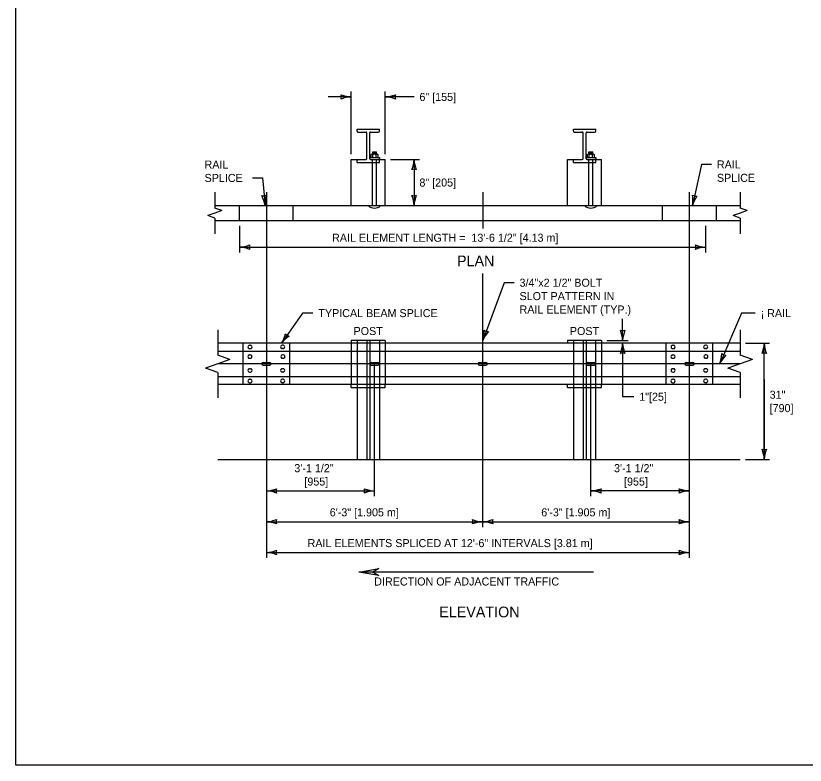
# Model space of a CAD drawing. Extents: x 49991.4 to 50021, y 49987.6 to 50011.4.
# Drawn here: x 49999.38 to 50005.28, y 49987.8 to 49993.4 of the extents above; entities that cross this region are included whole.
import ezdxf

# ---------------------------------------------------------------- set-up
doc = ezdxf.new("R2010")
doc.units = 0
for name, color, linetype in [('Level 1', 7, 'Continuous'), ('Level 2', 7, 'Continuous'), ('Level 3', 7, 'Continuous'), ('Level 4', 7, 'Continuous'), ('Level 5', 7, 'Continuous'), ('Level 6', 7, 'Continuous')]:
    doc.layers.add(name, color=color, linetype=linetype)

msp = doc.modelspace()

# ---------------------------------------------------------------- linework, layer by layer
at = {"layer": 'Level 1'}
for p, q in [((50001.9344, 49992.5525), (50002.101, 49992.5525)), ((50001.9344, 49992.5358), (50001.9344, 49992.5525)), ((50001.94, 49992.5302), (50002.0011, 49992.5302)), ((50002.0066, 49992.3307), (50002.0066, 49992.5247)), ((50002.0288, 49992.3307), (50002.0288, 49992.5247)), ((50002.0344, 49992.5302), (50002.0955, 49992.5302)), ((50002.101, 49992.5358), (50002.101, 49992.5525)), ((50003.5511, 49992.5525), (50003.7177, 49992.5525)), ((50003.5511, 49992.5358), (50003.5511, 49992.5525)), ((50003.5567, 49992.5302), (50003.6178, 49992.5302)), ((50003.6233, 49992.3307), (50003.6233, 49992.5247)), ((50003.6455, 49992.3307), (50003.6455, 49992.5247)), ((50003.6511, 49992.5302), (50003.7122, 49992.5302)), ((50003.7177, 49992.5358), (50003.7177, 49992.5525)), ((50001.8906, 49991.9808), (50001.8906, 49992.3252)), ((50001.8906, 49992.3252), (50001.9344, 49992.3252)), ((50001.9344, 49992.303), (50001.9344, 49992.3252)), ((50001.94, 49992.3251), (50002.0011, 49992.3251)), ((50002.0288, 49992.3393), (50002.1027, 49992.3393)), ((50002.0344, 49992.3251), (50002.0955, 49992.3251)), ((50002.0371, 49992.3601), (50002.0371, 49992.3393)), ((50002.0852, 49992.3641), (50002.0449, 49992.364)), ((50002.0509, 49992.3818), (50002.0793, 49992.3818)), ((50002.0509, 49992.364), (50002.0509, 49992.3818)), ((50002.0509, 49992.3801), (50002.0793, 49992.3776)), ((50002.0509, 49992.3748), (50002.0793, 49992.3725)), ((50002.0509, 49992.3692), (50002.0793, 49992.3669)), ((50002.0525, 49992.3393), (50002.0525, 49992.3602)), ((50002.0775, 49992.3393), (50002.0775, 49992.36)), ((50002.0793, 49992.3641), (50002.0793, 49992.3818)), ((50002.0929, 49992.3393), (50002.0929, 49992.3602)), ((50002.101, 49992.303), (50002.101, 49992.3252)), ((50002.101, 49992.3252), (50002.1447, 49992.3252)), ((50002.1027, 49992.3393), (50002.1027, 49992.3252)), ((50002.1447, 49991.9808), (50002.1447, 49992.3252)), ((50003.5073, 49991.9808), (50003.5073, 49992.3252)), ((50003.5073, 49992.3252), (50003.5511, 49992.3252)), ((50003.5511, 49992.303), (50003.5511, 49992.3252)), ((50003.5567, 49992.3251), (50003.6178, 49992.3251)), ((50003.6455, 49992.3393), (50003.7194, 49992.3393)), ((50003.6511, 49992.3251), (50003.7122, 49992.3251)), ((50003.6538, 49992.3601), (50003.6538, 49992.3393)), ((50003.7019, 49992.3641), (50003.6616, 49992.364)), ((50003.6676, 49992.3818), (50003.696, 49992.3818)), ((50003.6676, 49992.364), (50003.6676, 49992.3818)), ((50003.6676, 49992.3801), (50003.696, 49992.3776)), ((50003.6676, 49992.3748), (50003.696, 49992.3725)), ((50003.6676, 49992.3692), (50003.696, 49992.3669)), ((50003.6692, 49992.3393), (50003.6692, 49992.3602)), ((50003.6942, 49992.3393), (50003.6942, 49992.36)), ((50003.696, 49992.3641), (50003.696, 49992.3818)), ((50003.7096, 49992.3393), (50003.7096, 49992.3602)), ((50003.7177, 49992.303), (50003.7177, 49992.3252)), ((50003.7177, 49992.3252), (50003.7614, 49992.3252)), ((50003.7194, 49992.3393), (50003.7194, 49992.3252)), ((50003.7614, 49991.9808), (50003.7614, 49992.3252)), ((50001.9344, 49992.303), (50002.101, 49992.303)), ((50003.5511, 49992.303), (50003.7177, 49992.303)), ((50000.872, 49991.9808), (50004.7972, 49991.9808)), ((50001.0555, 49991.8697), (50001.0555, 49991.9808)), ((50004.2174, 49991.8697), (50004.2174, 49991.9808)), ((50000.872, 49991.8697), (50004.7972, 49991.8697)), ((50001.8905, 49990.9734), (50001.8905, 49990.9514)), ((50002.1446, 49990.9734), (50001.8905, 49990.9734)), ((50002.1446, 49990.9734), (50002.1446, 49990.9514)), ((50003.5072, 49990.9734), (50003.5072, 49990.9514)), ((50003.7613, 49990.9734), (50003.5072, 49990.9734)), ((50003.7613, 49990.9734), (50003.7613, 49990.9514)), ((50004.7972, 49990.9514), (50000.8926, 49990.9514)), ((50001.0822, 49990.6438), (50001.0822, 49990.9514)), ((50001.1314, 49990.9371), (50001.1374, 49990.9371)), ((50001.1314, 49990.9119), (50001.1374, 49990.9119)), ((50001.3815, 49990.9371), (50001.3754, 49990.9371)), ((50001.3815, 49990.9119), (50001.3754, 49990.9119)), ((50004.2441, 49990.6438), (50004.2441, 49990.9514)), ((50004.2933, 49990.9371), (50004.2993, 49990.9371)), ((50004.2933, 49990.9119), (50004.2993, 49990.9119)), ((50004.5434, 49990.9371), (50004.5373, 49990.9371)), ((50004.5434, 49990.9119), (50004.5373, 49990.9119)), ((50004.7972, 49990.8913), (50000.8926, 49990.8913)), ((50001.1301, 49990.8647), (50001.1362, 49990.8647)), ((50001.3827, 49990.8647), (50001.3767, 49990.8647)), ((50004.292, 49990.8647), (50004.2981, 49990.8647)), ((50004.5446, 49990.8647), (50004.5386, 49990.8647)), ((50001.1301, 49990.8395), (50001.1362, 49990.8395)), ((50001.2322, 49990.8092), (50001.2809, 49990.8092)), ((50001.3827, 49990.8395), (50001.3767, 49990.8395)), ((50002.0406, 49990.8092), (50002.0892, 49990.8092)), ((50002.8489, 49990.8092), (50002.8976, 49990.8092)), ((50003.6573, 49990.8092), (50003.7059, 49990.8092)), ((50004.292, 49990.8395), (50004.2981, 49990.8395)), ((50004.3941, 49990.8092), (50004.4428, 49990.8092)), ((50004.5446, 49990.8395), (50004.5386, 49990.8395)), ((50001.1315, 49990.7613), (50001.1376, 49990.7613)), ((50001.1315, 49990.7361), (50001.1376, 49990.7361)), ((50001.2322, 49990.7884), (50001.2809, 49990.7884)), ((50001.3813, 49990.7613), (50001.3753, 49990.7613)), ((50001.3813, 49990.7361), (50001.3753, 49990.7361)), ((50002.0406, 49990.7884), (50002.0892, 49990.7884)), ((50002.8489, 49990.7884), (50002.8976, 49990.7884)), ((50003.6573, 49990.7884), (50003.7059, 49990.7884)), ((50004.2934, 49990.7613), (50004.2995, 49990.7613)), ((50004.2934, 49990.7361), (50004.2995, 49990.7361)), ((50004.3941, 49990.7884), (50004.4428, 49990.7884)), ((50004.5432, 49990.7613), (50004.5372, 49990.7613)), ((50004.5432, 49990.7361), (50004.5372, 49990.7361)), ((50004.7972, 49990.7013), (50000.8926, 49990.7013)), ((50001.1313, 49990.6825), (50001.1374, 49990.6825)), ((50001.3815, 49990.6825), (50001.3754, 49990.6825)), ((50004.2932, 49990.6825), (50004.2993, 49990.6825)), ((50004.5434, 49990.6825), (50004.5373, 49990.6825)), ((50004.7972, 49990.6438), (50000.8926, 49990.6438)), ((50001.1313, 49990.6573), (50001.1374, 49990.6573)), ((50001.3815, 49990.6573), (50001.3754, 49990.6573)), ((50001.8905, 49990.6218), (50001.8905, 49990.6438)), ((50001.8905, 49990.6218), (50002.1446, 49990.6218)), ((50001.9343, 49990.6218), (50001.9343, 49990.0834)), ((50002.1009, 49990.6218), (50002.1009, 49990.0834)), ((50002.1446, 49990.6218), (50002.1446, 49990.6438)), ((50003.5072, 49990.6218), (50003.5072, 49990.6438)), ((50003.5072, 49990.6218), (50003.7613, 49990.6218)), ((50003.551, 49990.6218), (50003.551, 49990.0834)), ((50003.7176, 49990.6218), (50003.7176, 49990.0834)), ((50003.7613, 49990.6218), (50003.7613, 49990.6438)), ((50004.2932, 49990.6573), (50004.2993, 49990.6573)), ((50004.5434, 49990.6573), (50004.5373, 49990.6573)), ((50000.8926, 49990.0834), (50004.7972, 49990.0834))]:
    msp.add_line(p, q, dxfattribs=at)
msp.add_lwpolyline([(49999.3835, 49998.9992), (50016.7501, 49998.9992), (50016.7501, 49987.7988), (49999.3835, 49987.7988)], close=True, dxfattribs=at)
for centre, radius, start, end in [((50001.94, 49992.5358), 0.00555, 180, 270), ((50002.0011, 49992.5247), 0.00555, 360, 90), ((50002.0344, 49992.5247), 0.00555, 90, 180), ((50002.0955, 49992.5358), 0.00555, 270, 360), ((50003.5567, 49992.5358), 0.00555, 180, 270), ((50003.6178, 49992.5247), 0.00555, 360, 90), ((50003.6511, 49992.5247), 0.00555, 90, 180), ((50003.7122, 49992.5358), 0.00555, 270, 360), ((50001.94, 49992.3196), 0.00555, 90, 177.19225), ((50002.0011, 49992.3307), 0.00555, 270, 360), ((50002.0344, 49992.3307), 0.00555, 180, 270), ((50002.0448, 49992.3543), 0.00966, 37.32412, 143.10465), ((50002.0649, 49992.3428), 0.0213, 53.6874, 125.33876), ((50002.0853, 49992.3547), 0.00937, 35.4686, 145.97891), ((50002.0955, 49992.3196), 0.00555, 2.80775, 90), ((50003.5567, 49992.3196), 0.00555, 90, 177.19225), ((50003.6178, 49992.3307), 0.00555, 270, 360), ((50003.6511, 49992.3307), 0.00555, 180, 270), ((50003.6615, 49992.3543), 0.00966, 37.32412, 143.10465), ((50003.6816, 49992.3428), 0.0213, 53.6874, 125.33876), ((50003.702, 49992.3547), 0.00937, 35.4686, 145.97891), ((50003.7122, 49992.3196), 0.00555, 2.80775, 90), ((50001.2322, 49990.7988), 0.0104, 90, 180), ((50001.2322, 49990.7988), 0.0104, 180, 270), ((50001.2809, 49990.7988), 0.0104, 360, 90), ((50001.2809, 49990.7988), 0.0104, 270, 0), ((50002.0406, 49990.7988), 0.0104, 90, 180), ((50002.0406, 49990.7988), 0.0104, 180, 270), ((50002.0892, 49990.7988), 0.0104, 360, 90), ((50002.0892, 49990.7988), 0.0104, 270, 0), ((50002.8489, 49990.7988), 0.0104, 90, 180), ((50002.8489, 49990.7988), 0.0104, 180, 270), ((50002.8976, 49990.7988), 0.0104, 360, 90), ((50002.8976, 49990.7988), 0.0104, 270, 0), ((50003.6573, 49990.7988), 0.0104, 90, 180), ((50003.6573, 49990.7988), 0.0104, 180, 270), ((50003.7059, 49990.7988), 0.0104, 360, 90), ((50003.7059, 49990.7988), 0.0104, 270, 0), ((50004.3941, 49990.7988), 0.0104, 90, 180), ((50004.3941, 49990.7988), 0.0104, 180, 270), ((50004.4428, 49990.7988), 0.0104, 360, 90), ((50004.4428, 49990.7988), 0.0104, 270, 0)]:
    msp.add_arc(centre, radius, start, end, dxfattribs=at)
for centre, major_axis, start_param, end_param in [((50001.1314, 49990.9245), (-0.0126, 0), 4.712389, 7.853982), ((50001.1374, 49990.9245), (-0.0126, 0), 1.570796, 4.712389), ((50001.3754, 49990.9245), (0.0126, 0), 1.570796, 4.712389), ((50001.3815, 49990.9245), (0.0126, 0), 4.712389, 7.853982), ((50004.2933, 49990.9245), (-0.0126, 0), 4.712389, 7.853982), ((50004.2993, 49990.9245), (-0.0126, 0), 1.570796, 4.712389), ((50004.5373, 49990.9245), (0.0126, 0), 1.570796, 4.712389), ((50004.5434, 49990.9245), (0.0126, 0), 4.712389, 7.853982), ((50001.1301, 49990.8521), (-0.0126, 0), 4.712389, 7.853982), ((50001.1362, 49990.8521), (-0.0126, 0), 1.570796, 4.712389), ((50001.3767, 49990.8521), (0.0126, 0), 1.570796, 4.712389), ((50001.3827, 49990.8521), (0.0126, 0), 4.712389, 7.853982), ((50004.292, 49990.8521), (-0.0126, 0), 4.712389, 7.853982), ((50004.2981, 49990.8521), (-0.0126, 0), 1.570796, 4.712389), ((50004.5386, 49990.8521), (0.0126, 0), 1.570796, 4.712389), ((50004.5446, 49990.8521), (0.0126, 0), 4.712389, 7.853982), ((50001.1315, 49990.7487), (-0.0126, 0), 4.712389, 7.853982), ((50001.1376, 49990.7487), (-0.0126, 0), 1.570796, 4.712389), ((50001.3753, 49990.7487), (0.0126, 0), 1.570796, 4.712389), ((50001.3813, 49990.7487), (0.0126, 0), 4.712389, 7.853982), ((50004.2934, 49990.7487), (-0.0126, 0), 4.712389, 7.853982), ((50004.2995, 49990.7487), (-0.0126, 0), 1.570796, 4.712389), ((50004.5372, 49990.7487), (0.0126, 0), 1.570796, 4.712389), ((50004.5432, 49990.7487), (0.0126, 0), 4.712389, 7.853982), ((50001.1313, 49990.6699), (-0.0126, 0), 4.712389, 7.853982), ((50001.1374, 49990.6699), (-0.0126, 0), 1.570796, 4.712389), ((50001.3754, 49990.6699), (0.0126, 0), 1.570796, 4.712389), ((50001.3815, 49990.6699), (0.0126, 0), 4.712389, 7.853982), ((50004.2932, 49990.6699), (-0.0126, 0), 4.712389, 7.853982), ((50004.2993, 49990.6699), (-0.0126, 0), 1.570796, 4.712389), ((50004.5373, 49990.6699), (0.0126, 0), 1.570796, 4.712389), ((50004.5434, 49990.6699), (0.0126, 0), 4.712389, 7.853982)]:
    msp.add_ellipse(centre, major_axis=major_axis, ratio=0.998676, start_param=start_param, end_param=end_param, dxfattribs=at)
at = {"layer": 'Level 3'}
for p, q in [((50001.8906, 49992.3652), (50001.8906, 49992.8325)), ((50002.1447, 49992.3652), (50002.1447, 49992.8325)), ((50001.8906, 49992.7925), (50001.7172, 49992.7925)), ((50002.3604, 49992.7925), (50002.1447, 49992.7925)), ((50002.1847, 49992.3252), (50002.4004, 49992.3252)), ((50002.3604, 49992.3252), (50002.3604, 49991.9808)), ((50004.5097, 49992.2882), (50004.4415, 49991.9808)), ((50004.5838, 49992.2882), (50004.5097, 49992.2882)), ((50001.1524, 49992.1874), (50001.2265, 49992.1874)), ((50001.2265, 49992.1874), (50001.2465, 49991.9808)), ((50001.0555, 49991.8297), (50001.0555, 49991.6305)), ((50004.5392, 49991.8297), (50004.5392, 49991.6305)), ((50001.0555, 49991.6705), (50004.5392, 49991.6705)), ((50003.0345, 49991.4043), (50002.8733, 49990.9734)), ((50003.1086, 49991.4043), (50003.0345, 49991.4043)), ((50001.527, 49991.1772), (50001.3693, 49990.9514)), ((50001.6049, 49991.1772), (50001.527, 49991.1772)), ((50004.8081, 49991.1772), (50004.6447, 49990.7988)), ((50004.9105, 49991.1772), (50004.8081, 49991.1772)), ((50003.9193, 49990.9734), (50003.9193, 49991.1336)), ((50003.8013, 49990.9734), (50003.9593, 49990.9734)), ((50003.9193, 49990.9514), (50003.9193, 49990.5523)), ((50004.8372, 49990.9514), (50005.018, 49990.9514)), ((50004.978, 49990.0834), (50004.978, 49990.9514)), ((50004.978, 49990.681), (50004.978, 49990.0903)), ((50004.0033, 49990.5523), (50003.9193, 49990.5523)), ((50004.8372, 49990.0834), (50005.018, 49990.0834)), ((50001.2566, 49989.8485), (50002.0649, 49989.8485)), ((50004.4185, 49989.8485), (50003.6816, 49989.8485)), ((50001.2566, 49989.6185), (50002.8733, 49989.6185)), ((50002.8733, 49989.6185), (50004.4185, 49989.6185)), ((50001.2566, 49989.3885), (50004.4185, 49989.3885)), ((50003.7011, 49989.2417), (50001.948, 49989.2417))]:
    msp.add_line(p, q, dxfattribs=at)
msp.add_lwpolyline([(50002.0969, 49989.2155), (50001.948, 49989.2417), (50002.0969, 49989.2681), (50002.0515, 49989.2417)], close=True, dxfattribs=at)
for centre, radius, start, end in [((50001.8998, 49993.0146), 0.2223, 247.45601, 267.63952), ((50001.7624, 49992.7925), 0.0548, 342.13882, 17.86118), ((50002.1332, 49993.0252), 0.233, 272.82731, 292.07716), ((50002.2729, 49992.7925), 0.0548, 162.13882, 197.86118), ((50001.9021, 49992.5598), 0.233, 92.82731, 112.07716), ((50002.1355, 49992.5704), 0.2223, 67.45601, 87.63952), ((50002.1382, 49992.3344), 0.2223, 337.45601, 357.63952), ((50002.5931, 49992.3367), 0.233, 182.82731, 202.07716), ((50002.3604, 49992.197), 0.0548, 72.13882, 107.86118), ((50001.2341, 49992.1084), 0.0548, 257.6606, 293.38296), ((50001.016, 49991.947), 0.233, 8.34909, 27.59894), ((50001.4685, 49991.9931), 0.2223, 162.97779, 183.1613), ((50002.3604, 49992.109), 0.0548, 252.13882, 287.86118), ((50002.1276, 49991.9693), 0.233, 2.82731, 22.07716), ((50002.5825, 49991.9716), 0.2223, 157.45601, 177.63952), ((50004.2226, 49992.02), 0.2223, 349.84315, 10.02666), ((50004.6662, 49991.9191), 0.233, 145.40551, 164.65536), ((50004.4693, 49992.106), 0.0548, 239.62149, 275.34385), ((50001.044, 49991.9032), 0.233, 272.82731, 292.07716), ((50001.1837, 49991.6705), 0.0548, 162.13882, 197.86118), ((50004.5483, 49991.8927), 0.2223, 247.45601, 267.63952), ((50004.4109, 49991.6705), 0.0548, 342.13882, 17.86118), ((50001.0463, 49991.4484), 0.2223, 67.45601, 87.63952), ((50004.5506, 49991.4378), 0.233, 92.82731, 112.07716), ((50002.6513, 49991.0442), 0.233, 342.30809, 1.55794), ((50003.0781, 49990.887), 0.2223, 136.93679, 157.1203), ((50002.9182, 49991.0935), 0.0548, 231.6196, 267.34196), ((50003.6971, 49990.9642), 0.2223, 2.36048, 22.54399), ((50003.9193, 49991.1016), 0.0548, 252.13882, 287.86118), ((50004.152, 49990.9619), 0.233, 157.92284, 177.17269), ((50001.1719, 49991.0753), 0.233, 327.88526, 347.13511), ((50001.5461, 49990.8167), 0.2223, 122.51396, 142.69747), ((50001.4427, 49991.0565), 0.0548, 217.19677, 252.91913), ((50003.6971, 49990.9606), 0.2223, 337.45601, 357.63952), ((50004.152, 49990.9629), 0.233, 182.82731, 202.07716), ((50004.7559, 49990.9606), 0.2223, 337.45601, 357.63952), ((50005.2107, 49990.9629), 0.233, 182.82731, 202.07716), ((50003.9193, 49990.8232), 0.0548, 72.13882, 107.86118), ((50004.4265, 49990.8805), 0.233, 339.4694, 358.71925), ((50004.845, 49990.7023), 0.2223, 134.0981, 154.28161), ((50004.6955, 49990.9165), 0.0548, 228.78091, 264.50327), ((50004.978, 49990.8232), 0.0548, 72.13882, 107.86118), ((50004.978, 49990.2116), 0.0548, 252.13882, 287.86118), ((50004.7453, 49990.0719), 0.233, 2.82731, 22.07716), ((50005.2001, 49990.0742), 0.2223, 157.45601, 177.63952), ((50001.2451, 49990.0812), 0.233, 272.82731, 292.07716), ((50001.2474, 49989.6263), 0.2223, 67.45601, 87.63952), ((50001.3848, 49989.8485), 0.0548, 162.13882, 197.86118), ((50002.0741, 49990.0706), 0.2223, 247.45601, 267.63952), ((50001.9367, 49989.8485), 0.0548, 342.13882, 17.86118), ((50002.0764, 49989.6157), 0.233, 92.82731, 112.07716), ((50003.6724, 49990.0706), 0.2223, 272.36048, 292.54399), ((50003.6701, 49989.6157), 0.233, 67.92284, 87.17269), ((50003.8098, 49989.8485), 0.0548, 162.13882, 197.86118), ((50004.2902, 49989.8485), 0.0548, 342.13882, 17.86118), ((50004.4299, 49990.0812), 0.233, 247.92284, 267.17269), ((50004.4276, 49989.6263), 0.2223, 92.36048, 112.54399), ((50001.2451, 49989.8512), 0.233, 272.82731, 292.07716), ((50001.2474, 49989.3963), 0.2223, 67.45601, 87.63952), ((50001.3848, 49989.6185), 0.0548, 162.13882, 197.86118), ((50002.8824, 49989.8406), 0.2223, 247.45601, 267.63952), ((50002.745, 49989.6185), 0.0548, 342.13882, 17.86118), ((50002.8847, 49989.3857), 0.233, 92.82731, 112.07716), ((50002.8618, 49989.8512), 0.233, 272.82731, 292.07716), ((50002.8641, 49989.3963), 0.2223, 67.45601, 87.63952), ((50003.0015, 49989.6185), 0.0548, 162.13882, 197.86118), ((50004.4276, 49989.8406), 0.2223, 247.45601, 267.63952), ((50004.2902, 49989.6185), 0.0548, 342.13882, 17.86118), ((50004.4299, 49989.3857), 0.233, 92.82731, 112.07716), ((50001.2451, 49989.6212), 0.233, 272.82731, 292.07716), ((50001.2474, 49989.1663), 0.2223, 67.45601, 87.63952), ((50001.3848, 49989.3885), 0.0548, 162.13882, 197.86118), ((50004.4276, 49989.6106), 0.2223, 247.45601, 267.63952), ((50004.2902, 49989.3885), 0.0548, 342.13882, 17.86118), ((50004.4299, 49989.1557), 0.233, 92.82731, 112.07716)]:
    msp.add_arc(centre, radius, start, end, dxfattribs=at)
at = {"layer": 'Level 4'}
for p, q in [((50002.0508, 49991.9808), (50002.0508, 49992.3251)), ((50002.079, 49991.9808), (50002.079, 49992.3251)), ((50003.6675, 49991.9808), (50003.6675, 49992.3251)), ((50003.6957, 49991.9808), (50003.6957, 49992.3251)), ((50001.4577, 49991.8697), (50001.4577, 49991.9808)), ((50004.6196, 49991.8697), (50004.6196, 49991.9808)), ((50001.9343, 49990.9734), (50001.9343, 49990.6218)), ((50002.0065, 49990.9734), (50002.0065, 49990.0834)), ((50002.0287, 49990.9734), (50002.0287, 49990.0834)), ((50002.1009, 49990.9734), (50002.1009, 49990.6218)), ((50003.551, 49990.9734), (50003.551, 49990.6218)), ((50003.6232, 49990.9734), (50003.6232, 49990.0834)), ((50003.6454, 49990.9734), (50003.6454, 49990.0834)), ((50003.7176, 49990.9734), (50003.7176, 49990.6218)), ((50001.4306, 49990.6438), (50001.4306, 49990.9514)), ((50001.8905, 49990.9514), (50001.8905, 49990.6438)), ((50002.1446, 49990.9514), (50002.1446, 49990.6438)), ((50003.7613, 49990.9514), (50003.7613, 49990.6438)), ((50004.5925, 49990.6438), (50004.5925, 49990.9514))]:
    msp.add_line(p, q, dxfattribs=at)
for centre in [(50002.0648, 49992.0302), (50003.6815, 49992.0302)]:
    msp.add_arc(centre, 0.0682, 226.38418, 313.61582, dxfattribs=at)
at = {"layer": 'Level 5'}
for p, q in [((50001.2566, 49992.0808), (50001.2566, 49989.3485)), ((50002.8733, 49992.0808), (50002.8733, 49991.8105)), ((50004.4185, 49989.3485), (50004.4185, 49992.0808)), ((50002.8733, 49989.5785), (50002.8733, 49991.4722)), ((50004.8005, 49990.7988), (50000.8959, 49990.7988)), ((50002.0649, 49989.8085), (50002.0649, 49990.7988)), ((50003.6816, 49989.8085), (50003.6816, 49990.7988))]:
    msp.add_line(p, q, dxfattribs=at)
at = {"layer": 'Level 6'}
for p, q in [((50000.872, 49992.0808), (50000.872, 49991.9618)), ((50004.7972, 49992.0808), (50004.7972, 49991.9618)), ((50000.872, 49991.9247), (50000.8197, 49991.9062)), ((50000.9244, 49991.9433), (50000.872, 49991.9618)), ((50000.9244, 49991.9433), (50000.872, 49991.9247)), ((50004.7972, 49991.9247), (50004.7449, 49991.9062)), ((50004.8496, 49991.9433), (50004.7972, 49991.9618)), ((50004.8496, 49991.9433), (50004.7972, 49991.9247)), ((50000.872, 49991.8876), (50000.8197, 49991.9062)), ((50000.872, 49991.8876), (50000.872, 49991.7697)), ((50004.7972, 49991.8876), (50004.7449, 49991.9062)), ((50004.7972, 49991.8876), (50004.7972, 49991.7697)), ((50000.8926, 49991.0514), (50000.8926, 49990.8624)), ((50004.7972, 49991.0514), (50004.7972, 49990.8624)), ((50000.984, 49990.83), (50000.8926, 49990.8624)), ((50004.8886, 49990.83), (50004.7972, 49990.8624)), ((50000.8926, 49990.7976), (50000.8012, 49990.7652)), ((50000.984, 49990.83), (50000.8926, 49990.7976)), ((50004.7972, 49990.7976), (50004.7058, 49990.7652)), ((50004.8886, 49990.83), (50004.7972, 49990.7976)), ((50000.8926, 49990.7328), (50000.8012, 49990.7652)), ((50000.8926, 49990.7328), (50000.8926, 49990.5438)), ((50004.7972, 49990.7328), (50004.7058, 49990.7652)), ((50004.7972, 49990.7328), (50004.7972, 49990.5438))]:
    msp.add_line(p, q, dxfattribs=at)

# ---------------------------------------------------------------- texts
at = {"layer": 'Level 2'}
for s, height, p in [('6" [155]', 0.06, (50002.4004, 49992.7625)), ('RAIL', 0.06, (50004.6238, 49992.2582)), ('SPLICE', 0.06, (50004.6238, 49992.1582)), ('8" [205]', 0.06, (50002.4004, 49992.123)), ('PLAN', 0.08, (50002.6814, 49991.5273)), ('3/4"x2 1/2" BOLT', 0.06, (50003.1486, 49991.3743)), ('SLOT PATTERN IN', 0.06, (50003.1486, 49991.2743)), ('TYPICAL BEAM SPLICE', 0.06, (50001.6449, 49991.1472)), ('RAIL ELEMENT (TYP.)', 0.06, (50003.1486, 49991.1743)), ('¡ RAIL', 0.06, (50004.9505, 49991.1472)), ('POST', 0.06, (50001.908, 49991.0134)), ('POST', 0.06, (50003.5247, 49991.0134)), ('31"', 0.06, (50005.018, 49990.5375)), ('[790]', 0.06, (50005.018, 49990.4373)), ('DIRECTION OF ADJACENT TRAFFIC', 0.06, (50002.0626, 49989.1417)), ('ELEVATION', 0.08, (50002.5485, 49988.9039))]:
    msp.add_text(s, height=height, dxfattribs=at).set_placement(p)
for s, p in [('RAIL', (50000.7944, 49992.2574)), ('SPLICE', (50000.7944, 49992.1574)), ('RAIL ELEMENT LENGTH =  13\'-6 1/2" [4.13 m]', (50001.7476, 49991.7105)), ('1"[25]', (50004.0433, 49990.5223)), ('3\'-1 1/2" ', (50001.4655, 49989.9885)), ('3\'-1 1/2" ', (50003.8548, 49989.9885)), ('[955]', (50001.5405, 49989.8885)), ('[955]', (50003.9298, 49989.8885)), ('6\'-3" [1.905 m]', (50001.73, 49989.6585)), ('6\'-3" [1.905 m]', (50003.3109, 49989.6585)), ('RAIL ELEMENTS SPLICED AT 12\'-6" INTERVALS [3.81 m]', (50001.5644, 49989.4285))]:
    msp.add_text(s, height=0.06, rotation=360, dxfattribs=at).set_placement(p)

doc.saveas('drawing.dxf')
